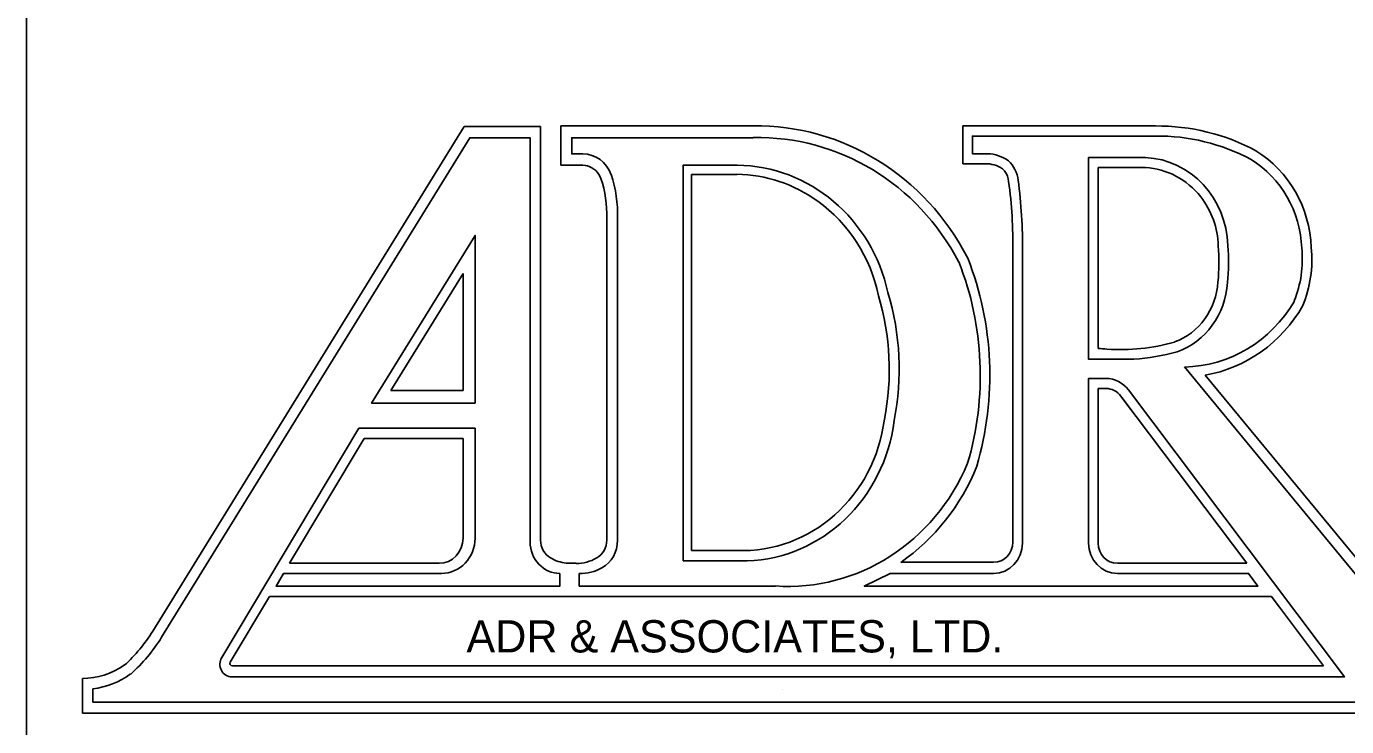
# Model space of a CAD drawing. Extents: x -6.4 to 34, y -1.2 to 22.
# Drawn here: x 32 to 33.31, y 3.463 to 4.158 of the extents above; entities that cross this region are included whole.
import ezdxf

# ---------------------------------------------------------------- set-up
doc = ezdxf.new("R2010")
doc.units = 0
doc.layers.add('GM_X_County', color=7, linetype='Continuous')
doc.layers.add('GM_X_Township', color=7, linetype='Continuous')

msp = doc.modelspace()

# ---------------------------------------------------------------- linework, layer by layer
at = {"layer": 'GM_X_County'}
msp.add_line((32, 0.5), (32, 21.5), dxfattribs=at)
at = {"layer": 'GM_X_Township'}
for p, q in [((32.1254, 3.558), (32.4341, 4.0584)), ((32.4341, 4.0584), (32.5101, 4.0584)), ((32.5101, 4.0435), (32.5101, 4.0584)), ((32.53, 4.059), (32.53, 4.02)), ((32.53, 4.059), (32.721, 4.059)), ((32.929, 4.059), (32.929, 4.0215)), ((32.929, 4.059), (33.12, 4.059)), ((32.929, 4.059), (32.929, 4.0215)), ((32.929, 4.059), (33.12, 4.059)), ((32.5101, 4.0435), (32.5101, 3.6481)), ((32.9432, 4.0215), (32.929, 4.0215)), ((32.9432, 4.0215), (32.929, 4.0215)), ((32.951, 4.0215), (32.9432, 4.0215)), ((32.5442, 4.02), (32.53, 4.02)), ((32.552, 4.02), (32.5442, 4.02)), ((32.7049, 4.011), (32.6598, 4.011)), ((32.6598, 4.011), (32.6598, 3.6379)), ((32.5757, 3.9673), (32.5757, 3.6481)), ((32.9785, 3.6462), (32.9785, 3.9347)), ((32.4331, 3.9128), (32.3615, 3.7966)), ((32.4331, 3.8944), (32.4331, 3.9128)), ((32.4331, 3.7966), (32.4331, 3.8944)), ((33.3849, 3.5506), (33.1692, 3.8119)), ((32.3615, 3.7966), (32.3728, 3.7966)), ((32.4331, 3.7966), (32.3728, 3.7966)), ((33.0868, 3.7896), (33.2106, 3.6252)), ((32.3351, 3.7491), (32.2609, 3.6252)), ((32.4331, 3.7491), (32.3351, 3.7491)), ((32.4331, 3.7366), (32.4331, 3.7491)), ((32.4331, 3.7366), (32.4331, 3.6502)), ((32.6598, 3.6379), (32.6683, 3.6379)), ((32.6683, 3.6379), (32.7049, 3.6379)), ((32.2609, 3.6252), (32.2722, 3.6252)), ((32.2722, 3.6252), (32.4094, 3.6252)), ((32.5384, 3.6252), (32.5356, 3.6254)), ((32.5384, 3.6252), (32.5356, 3.6254)), ((32.5384, 3.6252), (32.5453, 3.6252)), ((32.8673, 3.6262), (32.9595, 3.6262)), ((33.0822, 3.6252), (33.2106, 3.6252)), ((33.2351, 3.5922), (33.2867, 3.5234)), ((32.2043, 3.5234), (32.2112, 3.5234)), ((32.2112, 3.5234), (33.2867, 3.5234)), ((32.0556, 3.4766), (32.0556, 3.5109)), ((32.75, 3.5), (32.75, 3.5)), ((32.0556, 3.4766), (32.0701, 3.4766)), ((33.4404, 3.4766), (32.0701, 3.4766))]:
    msp.add_line(p, q, dxfattribs=at)
for points in [[(32.4996, 3.6463), (32.4996, 4.0474), (32.4398, 4.0474), (32.1341, 3.552)], [(32.721, 4.0474), (32.541, 4.0474), (32.541, 4.0313), (32.552, 4.0313)], [(33.12, 4.049), (32.9385, 4.049), (32.9385, 4.0315), (32.9536, 4.0315)], [(33.0537, 4.0278), (33.1102, 4.0278)], [(33.0987, 3.8276), (33.0537, 3.8276), (33.0537, 4.0278)], [(32.6514, 3.6276), (32.6514, 4.02), (32.7049, 4.02)], [(33.11, 4.0178), (33.0632, 4.0178), (33.0632, 3.8384)], [(32.5864, 3.9673), (32.5864, 3.9668), (32.5864, 3.6481)], [(32.445, 3.7841), (32.3424, 3.7841), (32.445, 3.9504), (32.445, 3.7841)], [(32.988, 3.9346), (32.988, 3.6452)], [(33.3772, 3.5431), (33.1487, 3.82)], [(33.0537, 3.6452), (33.0537, 3.8086), (33.0709, 3.8086)], [(33.0709, 3.7986), (33.0632, 3.7986), (33.0632, 3.6452)], [(33.0932, 3.7972), (33.3075, 3.5126), (32.2038, 3.5126)], [(33.0954, 3.7782), (33.0857, 3.791)], [(32.1938, 3.5318), (32.3298, 3.7591), (32.445, 3.7591), (32.445, 3.6502)], [(32.4118, 3.6152), (32.2551, 3.6152), (32.2476, 3.6027), (32.5292, 3.6027), (32.5292, 3.6152)], [(32.5484, 3.6152), (32.5484, 3.6027), (32.7432, 3.6027)], [(32.715, 3.6276), (32.6514, 3.6276)], [(32.9595, 3.6152), (32.857, 3.6152), (32.8311, 3.6027), (33.2217, 3.6027), (33.2123, 3.6152), (33.0822, 3.6152)], [(32.8673, 3.6262), (32.8894, 3.6262)], [(33.0822, 3.6252), (33.086, 3.6252)], [(33.2426, 3.5822), (33.2351, 3.5922), (32.2412, 3.5922), (32.2022, 3.5272)], [(32.066, 3.5006), (32.066, 3.4876), (33.4299, 3.4876), (33.4299, 3.5006)]]:
    msp.add_lwpolyline(points, dxfattribs=at)
for centre, major_axis, start_param, end_param in [((32.7243, 3.8082), (0, 0.2509), 5.209873, 6.297313), ((32.726, 3.8081), (0, 0.2394), 5.218006, 6.305445), ((33.1223, 3.8329), (0, 0.2261), 5.810103, 6.294452), ((33.1223, 3.8329), (0, 0.2261), 5.810103, 6.294452), ((33.1224, 3.8335), (0, 0.2155), 5.814829, 6.29527), ((33.1638, 3.9336), (0, 0.1167), 4.753214, 5.755325), ((33.1638, 3.9336), (0, 0.1167), 4.753214, 5.755325), ((32.552, 4), (0, 0.0313), 5.060756, 6.283185), ((32.9522, 3.9897), (0, 0.0318), 5.717883, 6.322951), ((32.9522, 3.9897), (0, 0.0418), 5.696071, 6.248499), ((32.9551, 4.0016), (0, 0.0304), 4.832872, 5.561833), ((33.1063, 3.9378), (0, 0.09), 4.740194, 6.23721), ((33.1638, 3.9336), (0, 0.1067), 4.750292, 5.755325), ((32.552, 4), (0, 0.02), 5.294753, 6.283185), ((32.552, 4), (0, 0.02), 5.060756, 5.294753), ((32.4775, 3.9716), (0, 0.1147), 4.675194, 5.060756), ((32.7039, 3.8572), (0, 0.1628), 4.938334, 6.276888), ((32.7028, 3.8574), (0, 0.1537), 5.684676, 6.268828), ((32.9551, 4.0016), (0, 0.0204), 5.34604, 5.529903), ((32.9551, 4.0016), (0, 0.0204), 4.827568, 5.34604), ((32.9551, 4.0016), (0, 0.0204), 4.827568, 5.34604), ((33.1063, 3.9378), (0, 0.08), 5.402738, 6.234422), ((32.4775, 3.9716), (0, 0.1034), 4.671123, 5.060756), ((32.5748, 3.9427), (0, 0.425), 4.693619, 4.857063), ((32.5748, 3.9427), (0, 0.425), 4.693619, 4.857063), ((32.5748, 3.9427), (0, 0.435), 4.693836, 4.856756), ((32.7028, 3.8574), (0, 0.1537), 4.930275, 5.684676), ((33.1063, 3.9378), (0, 0.08), 4.740194, 5.402738), ((33.1063, 3.9378), (0, 0.08), 4.740194, 5.402738), ((33.0035, 3.9239), (0, 0.1889), 4.608112, 4.797709), ((33.0035, 3.9239), (0, 0.1889), 4.608112, 4.797709), ((33.0086, 3.9238), (0, 0.1936), 4.607961, 4.797558), ((33.166, 3.9266), (0, 0.1049), 4.309756, 4.818512), ((33.166, 3.9266), (0, 0.1149), 4.303317, 4.815541), ((33.166, 3.9266), (0, 0.1149), 4.303317, 4.815541), ((32.6675, 3.8117), (0, 0.2934), 4.410917, 5.105556), ((32.6675, 3.8117), (0, 0.3034), 4.410917, 5.105556), ((33.1182, 3.9083), (0, -0.0672), 0.330696, 1.511334), ((33.1182, 3.9083), (0, -0.0672), 0.330696, 1.511334), ((33.1178, 3.9086), (0, -0.0777), 0.32607, 1.506707), ((32.6246, 3.8176), (0, 0.2435), 4.507644, 5.016706), ((32.626, 3.8177), (0, 0.2524), 4.509144, 5.018206), ((33.1467, 3.957), (0, -0.1371), 0.015856, 1.021186), ((33.1467, 3.957), (0, -0.1471), 0.16231, 1.026165), ((33.1467, 3.957), (0, -0.1471), 0.16231, 1.026165), ((33.0851, 4.056), (0, -0.2188), 6.177822, 6.219099), ((33.0851, 4.056), (0, -0.2188), 6.219099, 6.545404), ((33.0851, 4.056), (0, -0.2188), 6.219099, 6.545404), ((33.0851, 4.056), (0, -0.2288), 0.06267, 0.262218), ((33.0709, 3.7786), (0, 0.03), 5.382662, 6.283185), ((33.0709, 3.7786), (0, 0.02), 5.382662, 6.283185), ((32.7099, 3.7877), (0, -0.1499), 6.247489, 7.723), ((32.7099, 3.7877), (0, -0.1602), 0.033392, 1.439815), ((32.7557, 3.807), (0, -0.2047), 6.218561, 7.439351), ((32.7556, 3.8048), (0, -0.2139), 0.582172, 1.170799), ((32.4094, 3.6502), (0, -0.025), 0, 1.570796), ((32.4118, 3.6502), (0, -0.035), 0, 1.570796), ((32.5292, 3.6463), (0, -0.0311), 4.712389, 6.28383), ((32.5291, 3.6481), (0, -0.02), 4.712389, 5.785309), ((32.5567, 3.6481), (0, -0.02), 0.497877, 1.570796), ((32.5567, 3.6481), (0, -0.0313), 0.497877, 1.570796), ((32.9595, 3.6462), (0, -0.02), 0, 1.570796), ((32.9595, 3.6452), (0, -0.03), 0, 1.570796), ((33.0822, 3.6452), (0, -0.03), 4.712389, 6.283185), ((33.0822, 3.6452), (0, -0.02), 4.712389, 6.283185), ((32.5401, 3.6695), (0, -0.0444), 5.785308, 6.174936), ((32.5456, 3.6695), (0, -0.0444), 6.276852, 6.781063), ((32.5506, 3.6599), (0, -0.0447), 6.230381, 6.780961), ((31.9988, 3.6451), (0, -0.1592), 0.707735, 0.991966), ((31.9988, 3.6451), (0, -0.1702), 0.704048, 0.991966), ((32.0559, 3.5887), (0, -0.0777), 6.278764, 6.875053), ((32.2038, 3.5251), (0, -0.0125), 4.150117, 6.283185), ((32.2043, 3.5259), (0, -0.0025), 4.150111, 6.283185), ((32.0559, 3.5887), (0, -0.0887), 0.120377, 0.599173)]:
    msp.add_ellipse(centre, major_axis=major_axis, ratio=0.95, start_param=start_param, end_param=end_param, dxfattribs=at)

# ---------------------------------------------------------------- texts
msp.add_text('ADR & ASSOCIATES, LTD.', height=0.032, dxfattribs=at).set_placement((32.4365, 3.5368))

doc.saveas('drawing.dxf')
